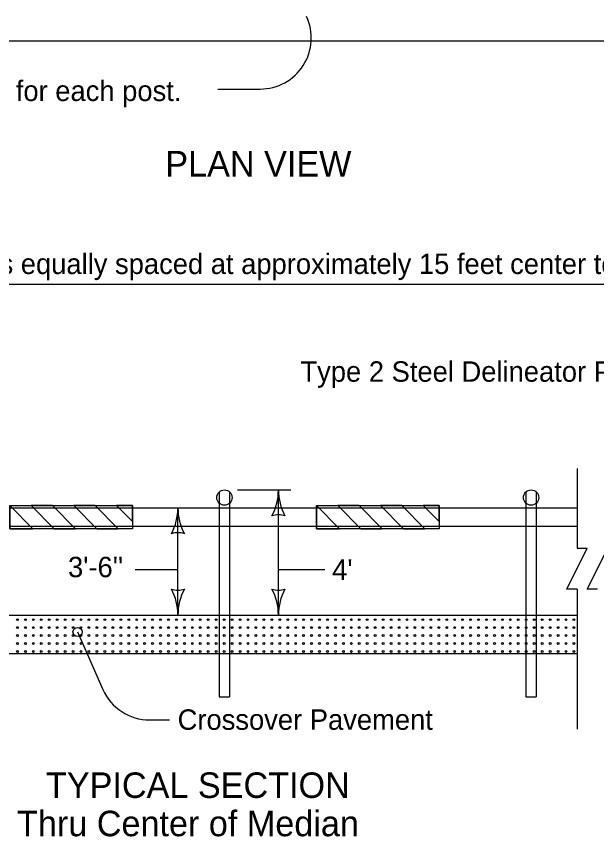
# Model space of a CAD drawing. Extents: x 228 to 3572, y -1307 to 1277.
# Drawn here: x 1248 to 1702, y -49 to 594 of the extents above; entities that cross this region are included whole.
import ezdxf

# ---------------------------------------------------------------- set-up
doc = ezdxf.new("R2010")
doc.units = 0
for name, color, linetype in [('dsnStdDimension', 7, 'Continuous'), ('Level 2', 7, 'Continuous'), ('Level 3', 7, 'Continuous')]:
    doc.layers.add(name, color=color, linetype=linetype)

msp = doc.modelspace()

# ---------------------------------------------------------------- linework, layer by layer
at = {"layer": 'dsnStdDimension'}
for p, q in [((1405.63, 536.87), (1438.86, 536.87)), ((690.89, 383.93), (2130.88, 383.93)), ((1421.24, 222.79), (1462.93, 222.79)), ((1453.14, 124.79), (1453.14, 222.79)), ((1374.48, 124.79), (1374.48, 208.79)), ((1340.94, 160.38), (1374.48, 160.38)), ((1453.14, 160.38), (1489.38, 160.38)), ((1295.93, 111.52), (1315.79, 66.48)), ((1352.38, 42.62), (1367.99, 42.62))]:
    msp.add_line(p, q, dxfattribs=at)
msp.add_circle((1295.93, 111.52), 3.56, dxfattribs=at)
for centre, radius, start, end in [((1438.86, 576.87), 40, 270, 24.98861), ((1409.96, 222.79), 43.18, 331.92751, 0), ((1496.32, 222.79), 43.18, 180, 208.07249), ((1331.3, 208.79), 43.18, 331.92751, 0), ((1417.66, 208.79), 43.18, 180, 208.07249), ((1453.14, 186.58), 16.68, 72.26665, 107.73335), ((1374.48, 172.58), 16.68, 72.26665, 107.73335), ((1374.48, 160.99), 16.68, 252.26665, 287.73335), ((1331.3, 124.79), 43.18, 0, 28.07249), ((1417.66, 124.79), 43.18, 151.92751, 180), ((1453.14, 160.99), 16.68, 252.26665, 287.73335), ((1409.96, 124.79), 43.18, 0, 28.07249), ((1496.32, 124.79), 43.18, 151.92751, 180), ((1352.38, 82.62), 40, 203.79608, 270)]:
    msp.add_arc(centre, radius, start, end, dxfattribs=at)
at = {"layer": 'Level 2'}
for p, q in [((519.47, 574.71), (2276.26, 574.71)), ((1686.88, 239.58), (1686.88, 177.25)), ((1406.89, 220.79), (1406.89, 124.79)), ((1414.89, 220.79), (1414.89, 124.79)), ((1646.88, 220.79), (1646.88, 124.79)), ((1654.88, 220.79), (1654.88, 124.79)), ((1134.89, 208.79), (1686.88, 208.79)), ((1259.58, 210.54), (1277.68, 192.44)), ((1276.27, 210.54), (1294.37, 192.44)), ((1292.95, 210.54), (1311.05, 192.44)), ((1309.65, 210.54), (1327.75, 192.44)), ((1326.33, 210.54), (1338.87, 198)), ((1482.89, 210.54), (1500.98, 192.44)), ((1499.58, 210.54), (1517.67, 192.44)), ((1516.27, 210.54), (1534.37, 192.44)), ((1532.95, 210.54), (1551.05, 192.44)), ((1549.65, 210.54), (1567.75, 192.44)), ((1566.33, 210.54), (1578.87, 198)), ((1134.89, 194.29), (1686.88, 194.29)), ((1678.88, 144.94), (1694.88, 177.25)), ((1686.88, 177.25), (1694.88, 177.25)), ((1694.88, 144.94), (1710.88, 177.25)), ((1686.88, 144.94), (1678.88, 144.94)), ((1686.88, 144.94), (1686.88, 124.79)), ((1702.88, 144.94), (1694.88, 144.94)), ((1134.89, 124.79), (1686.88, 124.79)), ((1134.89, 124.79), (1686.88, 124.79)), ((1134.89, 124.79), (1686.88, 124.79)), ((1406.89, 124.79), (1406.89, 60.79)), ((1414.89, 124.79), (1414.89, 60.79)), ((1646.88, 124.79), (1646.88, 60.79)), ((1654.88, 124.79), (1654.88, 60.79)), ((1686.88, 124.79), (1686.88, 94.49)), ((1686.88, 94.49), (1134.89, 94.49)), ((1686.88, 94.49), (1686.88, 35.46)), ((1406.89, 60.79), (1414.89, 60.79)), ((1646.88, 60.79), (1654.88, 60.79))]:
    msp.add_line(p, q, dxfattribs=at)
for points in [[(1242.89, 210.54), (1338.89, 210.54), (1338.89, 192.44), (1242.89, 192.44)], [(1242.89, 210.54), (1242.89, 192.44), (1260.99, 192.44)], [(1277.68, 192.44), (1294.37, 192.44), (1276.27, 210.54), (1259.58, 210.54)], [(1311.05, 192.44), (1327.75, 192.44), (1309.65, 210.54), (1292.95, 210.54)], [(1338.87, 198), (1338.87, 210.54), (1326.33, 210.54)], [(1482.89, 210.54), (1578.88, 210.54), (1578.88, 192.44), (1482.89, 192.44)], [(1482.89, 210.54), (1482.89, 192.44), (1500.98, 192.44)], [(1517.67, 192.44), (1534.37, 192.44), (1516.27, 210.54), (1499.58, 210.54)], [(1551.05, 192.44), (1567.75, 192.44), (1549.65, 210.54), (1532.95, 210.54)], [(1578.87, 198), (1578.87, 210.54), (1566.33, 210.54)]]:
    msp.add_lwpolyline(points, close=True, dxfattribs=at)
for centre, radius in [((1410.89, 216.79), 6), ((1650.88, 216.79), 6), ((1248.87, 121.15), 0.711), ((1255.09, 121.15), 0.711), ((1261.31, 121.15), 0.711), ((1267.54, 121.15), 0.711), ((1273.76, 121.15), 0.711), ((1279.98, 121.15), 0.711), ((1286.2, 121.15), 0.711), ((1292.43, 121.15), 0.711), ((1298.65, 121.15), 0.711), ((1304.87, 121.15), 0.711), ((1311.09, 121.15), 0.711), ((1317.31, 121.15), 0.711), ((1323.54, 121.15), 0.711), ((1329.76, 121.15), 0.711), ((1335.98, 121.15), 0.711), ((1342.2, 121.15), 0.711), ((1348.43, 121.15), 0.711), ((1354.65, 121.15), 0.711), ((1360.87, 121.15), 0.711), ((1367.09, 121.15), 0.711), ((1373.32, 121.15), 0.711), ((1379.54, 121.15), 0.711), ((1385.76, 121.15), 0.711), ((1391.98, 121.15), 0.711), ((1398.21, 121.15), 0.711), ((1404.43, 121.15), 0.711), ((1410.65, 121.15), 0.711), ((1416.87, 121.15), 0.711), ((1423.1, 121.15), 0.711), ((1429.32, 121.15), 0.711), ((1435.54, 121.15), 0.711), ((1441.76, 121.15), 0.711), ((1447.99, 121.15), 0.711), ((1454.21, 121.15), 0.711), ((1460.43, 121.15), 0.711), ((1466.65, 121.15), 0.711), ((1472.87, 121.15), 0.711), ((1479.1, 121.15), 0.711), ((1485.32, 121.15), 0.711), ((1491.54, 121.15), 0.711), ((1497.76, 121.15), 0.711), ((1503.99, 121.15), 0.711), ((1510.21, 121.15), 0.711), ((1516.43, 121.15), 0.711), ((1522.65, 121.15), 0.711), ((1528.88, 121.15), 0.711), ((1535.1, 121.15), 0.711), ((1541.32, 121.15), 0.711), ((1547.54, 121.15), 0.711), ((1553.77, 121.15), 0.711), ((1559.99, 121.15), 0.711), ((1566.21, 121.15), 0.711), ((1572.43, 121.15), 0.711), ((1578.66, 121.15), 0.711), ((1584.88, 121.15), 0.711), ((1591.1, 121.15), 0.711), ((1597.32, 121.15), 0.711), ((1603.54, 121.15), 0.711), ((1609.77, 121.15), 0.711), ((1615.99, 121.15), 0.711), ((1622.21, 121.15), 0.711), ((1628.43, 121.15), 0.711), ((1634.66, 121.15), 0.711), ((1640.88, 121.15), 0.711), ((1647.1, 121.15), 0.711), ((1653.32, 121.15), 0.711), ((1659.55, 121.15), 0.711), ((1665.77, 121.15), 0.711), ((1671.99, 121.15), 0.711), ((1678.21, 121.15), 0.711), ((1684.44, 121.15), 0.711), ((1248.87, 114.92), 0.711), ((1248.87, 108.7), 0.711), ((1255.09, 114.92), 0.711), ((1255.09, 108.7), 0.711), ((1261.31, 114.92), 0.711), ((1261.31, 108.7), 0.711), ((1267.54, 114.92), 0.711), ((1267.54, 108.7), 0.711), ((1273.76, 114.92), 0.711), ((1273.76, 108.7), 0.711), ((1279.98, 114.92), 0.711), ((1279.98, 108.7), 0.711), ((1286.2, 114.92), 0.711), ((1286.2, 108.7), 0.711), ((1292.43, 114.92), 0.711), ((1292.43, 108.7), 0.711), ((1298.65, 114.92), 0.711), ((1298.65, 108.7), 0.711), ((1304.87, 114.92), 0.711), ((1304.87, 108.7), 0.711), ((1311.09, 114.92), 0.711), ((1311.09, 108.7), 0.711), ((1317.31, 114.92), 0.711), ((1317.31, 108.7), 0.711), ((1323.54, 114.92), 0.711), ((1323.54, 108.7), 0.711), ((1329.76, 114.92), 0.711), ((1329.76, 108.7), 0.711), ((1335.98, 114.92), 0.711), ((1335.98, 108.7), 0.711), ((1342.2, 114.92), 0.711), ((1342.2, 108.7), 0.711), ((1348.43, 114.92), 0.711), ((1348.43, 108.7), 0.711), ((1354.65, 114.92), 0.711), ((1354.65, 108.7), 0.711), ((1360.87, 114.92), 0.711), ((1360.87, 108.7), 0.711), ((1367.09, 114.92), 0.711), ((1367.09, 108.7), 0.711), ((1373.32, 114.92), 0.711), ((1373.32, 108.7), 0.711), ((1379.54, 114.92), 0.711), ((1379.54, 108.7), 0.711), ((1385.76, 114.92), 0.711), ((1385.76, 108.7), 0.711), ((1391.98, 114.92), 0.711), ((1391.98, 108.7), 0.711), ((1398.21, 114.92), 0.711), ((1398.21, 108.7), 0.711), ((1404.43, 114.92), 0.711), ((1404.43, 108.7), 0.711), ((1410.65, 114.92), 0.711), ((1410.65, 108.7), 0.711), ((1416.87, 114.92), 0.711), ((1416.87, 108.7), 0.711), ((1423.1, 114.92), 0.711), ((1423.1, 108.7), 0.711), ((1429.32, 114.92), 0.711), ((1429.32, 108.7), 0.711), ((1435.54, 114.92), 0.711), ((1435.54, 108.7), 0.711), ((1441.76, 114.92), 0.711), ((1441.76, 108.7), 0.711), ((1447.99, 114.92), 0.711), ((1447.99, 108.7), 0.711), ((1454.21, 114.92), 0.711), ((1454.21, 108.7), 0.711), ((1460.43, 114.92), 0.711), ((1460.43, 108.7), 0.711), ((1466.65, 114.92), 0.711), ((1466.65, 108.7), 0.711), ((1472.87, 114.92), 0.711), ((1472.87, 108.7), 0.711), ((1479.1, 114.92), 0.711), ((1479.1, 108.7), 0.711), ((1485.32, 114.92), 0.711), ((1485.32, 108.7), 0.711), ((1491.54, 114.92), 0.711), ((1491.54, 108.7), 0.711), ((1497.76, 114.92), 0.711), ((1497.76, 108.7), 0.711), ((1503.99, 114.92), 0.711), ((1503.99, 108.7), 0.711), ((1510.21, 114.92), 0.711), ((1510.21, 108.7), 0.711), ((1516.43, 114.92), 0.711), ((1516.43, 108.7), 0.711), ((1522.65, 114.92), 0.711), ((1522.65, 108.7), 0.711), ((1528.88, 114.92), 0.711), ((1528.88, 108.7), 0.711), ((1535.1, 114.92), 0.711), ((1535.1, 108.7), 0.711), ((1541.32, 114.92), 0.711), ((1541.32, 108.7), 0.711), ((1547.54, 114.92), 0.711), ((1547.54, 108.7), 0.711), ((1553.77, 114.92), 0.711), ((1553.77, 108.7), 0.711), ((1559.99, 114.92), 0.711), ((1559.99, 108.7), 0.711), ((1566.21, 114.92), 0.711), ((1566.21, 108.7), 0.711), ((1572.43, 114.92), 0.711), ((1572.43, 108.7), 0.711), ((1578.66, 114.92), 0.711), ((1578.66, 108.7), 0.711), ((1584.88, 114.92), 0.711), ((1584.88, 108.7), 0.711), ((1591.1, 114.92), 0.711), ((1591.1, 108.7), 0.711), ((1597.32, 114.92), 0.711), ((1597.32, 108.7), 0.711), ((1603.54, 114.92), 0.711), ((1603.54, 108.7), 0.711), ((1609.77, 114.92), 0.711), ((1609.77, 108.7), 0.711), ((1615.99, 114.92), 0.711), ((1615.99, 108.7), 0.711), ((1622.21, 114.92), 0.711), ((1622.21, 108.7), 0.711), ((1628.43, 114.92), 0.711), ((1628.43, 108.7), 0.711), ((1634.66, 114.92), 0.711), ((1634.66, 108.7), 0.711), ((1640.88, 114.92), 0.711), ((1640.88, 108.7), 0.711), ((1647.1, 114.92), 0.711), ((1647.1, 108.7), 0.711), ((1653.32, 114.92), 0.711), ((1653.32, 108.7), 0.711), ((1659.55, 114.92), 0.711), ((1659.55, 108.7), 0.711), ((1665.77, 114.92), 0.711), ((1665.77, 108.7), 0.711), ((1671.99, 114.92), 0.711), ((1671.99, 108.7), 0.711), ((1678.21, 114.92), 0.711), ((1678.21, 108.7), 0.711), ((1684.44, 114.92), 0.711), ((1684.44, 108.7), 0.711), ((1248.87, 102.48), 0.711), ((1255.09, 102.48), 0.711), ((1261.31, 102.48), 0.711), ((1267.54, 102.48), 0.711), ((1273.76, 102.48), 0.711), ((1279.98, 102.48), 0.711), ((1286.2, 102.48), 0.711), ((1292.43, 102.48), 0.711), ((1298.65, 102.48), 0.711), ((1304.87, 102.48), 0.711), ((1311.09, 102.48), 0.711), ((1317.31, 102.48), 0.711), ((1323.54, 102.48), 0.711), ((1329.76, 102.48), 0.711), ((1335.98, 102.48), 0.711), ((1342.2, 102.48), 0.711), ((1348.43, 102.48), 0.711), ((1354.65, 102.48), 0.711), ((1360.87, 102.48), 0.711), ((1367.09, 102.48), 0.711), ((1373.32, 102.48), 0.711), ((1379.54, 102.48), 0.711), ((1385.76, 102.48), 0.711), ((1391.98, 102.48), 0.711), ((1398.21, 102.48), 0.711), ((1404.43, 102.48), 0.711), ((1410.65, 102.48), 0.711), ((1416.87, 102.48), 0.711), ((1423.1, 102.48), 0.711), ((1429.32, 102.48), 0.711), ((1435.54, 102.48), 0.711), ((1441.76, 102.48), 0.711), ((1447.99, 102.48), 0.711), ((1454.21, 102.48), 0.711), ((1460.43, 102.48), 0.711), ((1466.65, 102.48), 0.711), ((1472.87, 102.48), 0.711), ((1479.1, 102.48), 0.711), ((1485.32, 102.48), 0.711), ((1491.54, 102.48), 0.711), ((1497.76, 102.48), 0.711), ((1503.99, 102.48), 0.711), ((1510.21, 102.48), 0.711), ((1516.43, 102.48), 0.711), ((1522.65, 102.48), 0.711), ((1528.88, 102.48), 0.711), ((1535.1, 102.48), 0.711), ((1541.32, 102.48), 0.711), ((1547.54, 102.48), 0.711), ((1553.77, 102.48), 0.711), ((1559.99, 102.48), 0.711), ((1566.21, 102.48), 0.711), ((1572.43, 102.48), 0.711), ((1578.66, 102.48), 0.711), ((1584.88, 102.48), 0.711), ((1591.1, 102.48), 0.711), ((1597.32, 102.48), 0.711), ((1603.54, 102.48), 0.711), ((1609.77, 102.48), 0.711), ((1615.99, 102.48), 0.711), ((1622.21, 102.48), 0.711), ((1628.43, 102.48), 0.711), ((1634.66, 102.48), 0.711), ((1640.88, 102.48), 0.711), ((1647.1, 102.48), 0.711), ((1653.32, 102.48), 0.711), ((1659.55, 102.48), 0.711), ((1665.77, 102.48), 0.711), ((1671.99, 102.48), 0.711), ((1678.21, 102.48), 0.711), ((1684.44, 102.48), 0.711), ((1248.87, 96.26), 0.711), ((1255.09, 96.26), 0.711), ((1261.31, 96.26), 0.711), ((1267.54, 96.26), 0.711), ((1273.76, 96.26), 0.711), ((1279.98, 96.26), 0.711), ((1286.2, 96.26), 0.711), ((1292.43, 96.26), 0.711), ((1298.65, 96.26), 0.711), ((1304.87, 96.26), 0.711), ((1311.09, 96.26), 0.711), ((1317.31, 96.26), 0.711), ((1323.54, 96.26), 0.711), ((1329.76, 96.26), 0.711), ((1335.98, 96.26), 0.711), ((1342.2, 96.26), 0.711), ((1348.43, 96.26), 0.711), ((1354.65, 96.26), 0.711), ((1360.87, 96.26), 0.711), ((1367.09, 96.26), 0.711), ((1373.32, 96.26), 0.711), ((1379.54, 96.26), 0.711), ((1385.76, 96.26), 0.711), ((1391.98, 96.26), 0.711), ((1398.21, 96.26), 0.711), ((1404.43, 96.26), 0.711), ((1410.65, 96.26), 0.711), ((1416.87, 96.26), 0.711), ((1423.1, 96.26), 0.711), ((1429.32, 96.26), 0.711), ((1435.54, 96.26), 0.711), ((1441.76, 96.26), 0.711), ((1447.99, 96.26), 0.711), ((1454.21, 96.26), 0.711), ((1460.43, 96.26), 0.711), ((1466.65, 96.26), 0.711), ((1472.87, 96.26), 0.711), ((1479.1, 96.26), 0.711), ((1485.32, 96.26), 0.711), ((1491.54, 96.26), 0.711), ((1497.76, 96.26), 0.711), ((1503.99, 96.26), 0.711), ((1510.21, 96.26), 0.711), ((1516.43, 96.26), 0.711), ((1522.65, 96.26), 0.711), ((1528.88, 96.26), 0.711), ((1535.1, 96.26), 0.711), ((1541.32, 96.26), 0.711), ((1547.54, 96.26), 0.711), ((1553.77, 96.26), 0.711), ((1559.99, 96.26), 0.711), ((1566.21, 96.26), 0.711), ((1572.43, 96.26), 0.711), ((1578.66, 96.26), 0.711), ((1584.88, 96.26), 0.711), ((1591.1, 96.26), 0.711), ((1597.32, 96.26), 0.711), ((1603.54, 96.26), 0.711), ((1609.77, 96.26), 0.711), ((1615.99, 96.26), 0.711), ((1622.21, 96.26), 0.711), ((1628.43, 96.26), 0.711), ((1634.66, 96.26), 0.711), ((1640.88, 96.26), 0.711), ((1647.1, 96.26), 0.711), ((1653.32, 96.26), 0.711), ((1659.55, 96.26), 0.711), ((1665.77, 96.26), 0.711), ((1671.99, 96.26), 0.711), ((1678.21, 96.26), 0.711), ((1684.44, 96.26), 0.711)]:
    msp.add_circle(centre, radius, dxfattribs=at)

# ---------------------------------------------------------------- texts
at = {"layer": 'dsnStdDimension'}
for s, p in [("'' to 4'' diameter hole thru crossover pavement for each post.", (806.69, 527.46)), ('Variable (Delineator Posts equally spaced at approximately 15 feet center to center)', (997.02, 391.93)), ('Type 2 Steel Delineator Post', (1470.38, 307.56)), ("3'-6''", (1288.47, 154.41)), ("4'", (1495.2, 152.34)), ('Crossover Pavement', (1374.26, 34.87))]:
    msp.add_text(s, height=16, dxfattribs=at).set_placement(p)
at = {"layer": 'Level 3'}
for s, p in [('PLAN VIEW', (1364.63, 468.3)), ('TYPICAL SECTION', (1271.21, -18.51)), ('Thru Center of Median', (1248.57, -48.51))]:
    msp.add_text(s, height=20, dxfattribs=at).set_placement(p)

doc.saveas('drawing.dxf')
